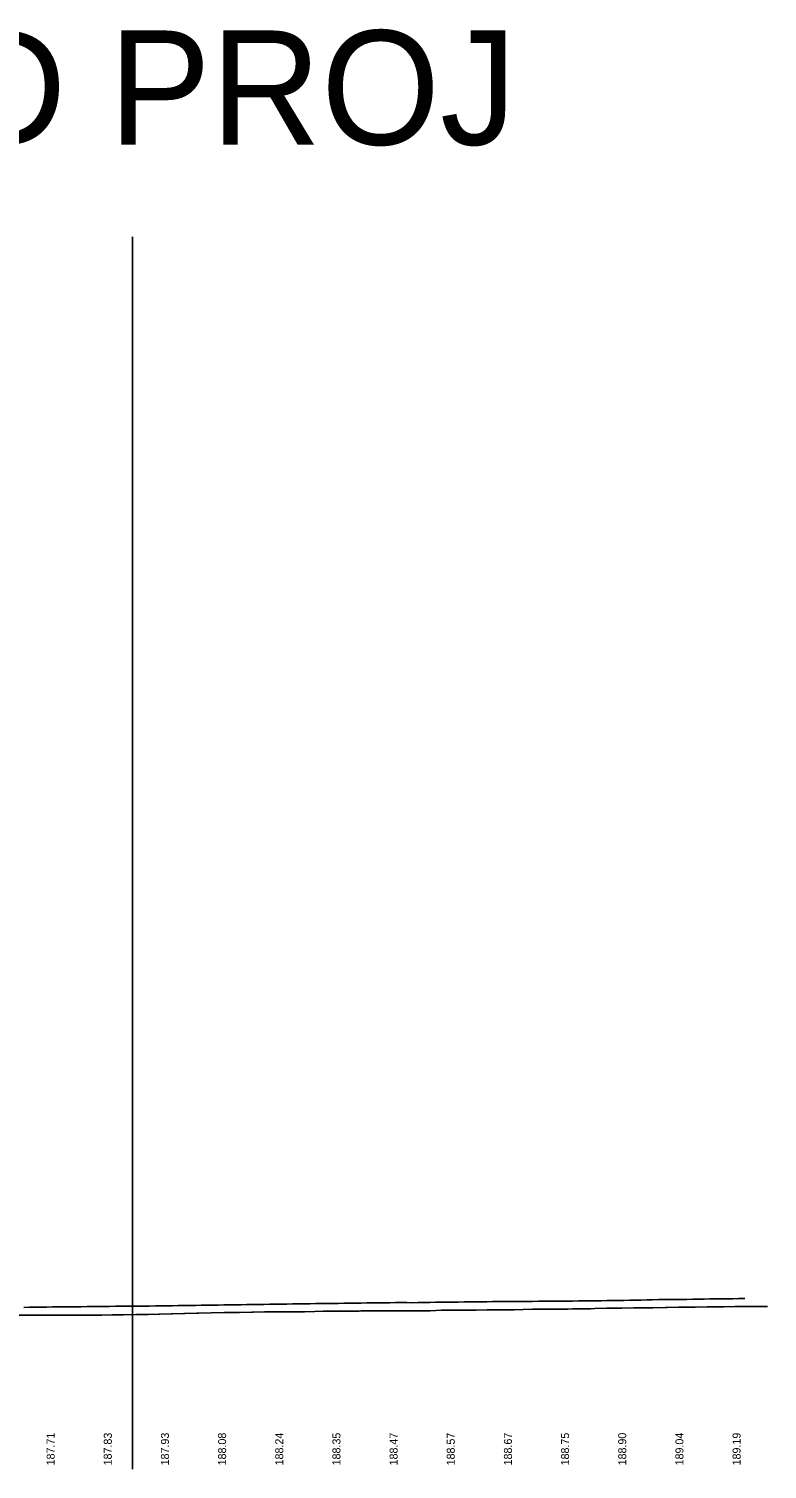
# Model space of a CAD drawing. Extents: x 1838386 to 1955906, y 719739 to 834437.
# Drawn here: x 1884140 to 1884785, y 820597 to 821857 of the extents above; entities that cross this region are included whole.
import ezdxf

# ---------------------------------------------------------------- set-up
doc = ezdxf.new("R2010")
doc.units = 0
for name, color, linetype in [('RD_DDB_Profile_EX', 7, 'Continuous'), ('RD_DDB_StripGrade', 7, 'Continuous'), ('RD_Sketch1', 7, 'Continuous')]:
    doc.layers.add(name, color=color, linetype=linetype)

msp = doc.modelspace()

# ---------------------------------------------------------------- linework, layer by layer
at = {"layer": 'RD_DDB_Profile_EX'}
for points in [[(1884135.2, 820738.3), (1884140.2, 820738.4), (1884145.2, 820738.5), (1884150.2, 820738.5), (1884155.2, 820738.6), (1884160.2, 820738.7), (1884165.2, 820738.7), (1884170.2, 820738.8), (1884175.2, 820738.8), (1884180.2, 820738.9), (1884185.2, 820738.9), (1884190.2, 820739), (1884195.2, 820739), (1884200.2, 820739.1), (1884205.2, 820739.1), (1884210.2, 820739.2), (1884215.2, 820739.3), (1884220.2, 820739.4), (1884225.2, 820739.4), (1884230.2, 820739.4), (1884235.2, 820739.4), (1884240.2, 820739.5), (1884245.2, 820739.5), (1884250.2, 820739.6), (1884255.2, 820739.6), (1884260.2, 820739.7), (1884265.2, 820739.8), (1884270.2, 820739.9), (1884275.2, 820740), (1884280.2, 820740), (1884285.2, 820740.1), (1884290.2, 820740.2), (1884295.2, 820740.3), (1884300.2, 820740.4), (1884305.2, 820740.4), (1884310.2, 820740.5), (1884315.2, 820740.6), (1884320.2, 820740.6), (1884325.2, 820740.7), (1884330.2, 820740.8), (1884335.2, 820740.9), (1884340.2, 820741), (1884345.2, 820741), (1884350.2, 820741.1), (1884355.2, 820741.2), (1884360.2, 820741.3), (1884365.2, 820741.3), (1884370.2, 820741.4), (1884375.2, 820741.5), (1884380.2, 820741.5), (1884385.2, 820741.5), (1884390.2, 820741.6)], [(1884390.2, 820741.6), (1884395.2, 820741.7), (1884400.2, 820741.7), (1884405.2, 820741.8), (1884410.2, 820741.8), (1884415.2, 820741.9), (1884420.2, 820742), (1884425.2, 820742.1), (1884430.2, 820742.1), (1884435.2, 820742.2), (1884440.2, 820742.3), (1884445.2, 820742.3), (1884450.2, 820742.4), (1884455.2, 820742.4), (1884460.2, 820742.5), (1884465.2, 820742.5), (1884470.2, 820742.5), (1884475.2, 820742.4), (1884480.2, 820742.5), (1884485.2, 820742.6), (1884490.2, 820742.7), (1884495.2, 820742.8), (1884500.2, 820742.8), (1884505.2, 820742.8), (1884510.2, 820742.9), (1884515.2, 820743), (1884520.2, 820743.1), (1884525.2, 820743.1), (1884530.2, 820743.1), (1884535.2, 820743.2), (1884540.2, 820743.3), (1884545.2, 820743.4), (1884550.2, 820743.4), (1884555.2, 820743.4), (1884560.2, 820743.5), (1884565.2, 820743.5), (1884570.2, 820743.5), (1884575.2, 820743.6), (1884580.2, 820743.6), (1884585.2, 820743.7), (1884590.2, 820743.7), (1884595.2, 820743.8), (1884600.2, 820743.8), (1884605.2, 820743.8), (1884610.2, 820743.9), (1884615.2, 820743.9), (1884620.2, 820744), (1884625.2, 820744), (1884630.2, 820744.1), (1884635.2, 820744.1), (1884640.2, 820744.2), (1884645.2, 820744.3), (1884650.2, 820744.3), (1884655.2, 820744.4), (1884660.2, 820744.5), (1884665.2, 820744.7), (1884670.2, 820744.7), (1884675.2, 820744.8), (1884680.2, 820744.9), (1884685.2, 820745), (1884690.2, 820745.1), (1884695.2, 820745.2), (1884700.2, 820745.2), (1884705.2, 820745.3), (1884710.2, 820745.3), (1884715.2, 820745.3), (1884720.2, 820745.4), (1884725.2, 820745.5), (1884730.2, 820745.6), (1884735.2, 820745.7), (1884740.2, 820745.7), (1884745.2, 820745.8), (1884750.2, 820745.9), (1884755.2, 820745.9), (1884760.2, 820746), (1884765.2, 820746.1), (1884765.7, 820746.1)]]:
    msp.add_lwpolyline(points, dxfattribs=at)
at = {"layer": 'RD_Sketch1'}
msp.add_line((1884230.2, 820596.8), (1884230.2, 821674.8), dxfattribs=at)
msp.add_line((1884230.2, 820596.8), (1884230.2, 821674.8), dxfattribs=at)
msp.add_line((1884230.2, 820596.8), (1884230.2, 821674.8), dxfattribs=at)
msp.add_lwpolyline([(1884131.1, 820731.4), (1884141.9, 820731.5), (1884142.4, 820731.5), (1884154.1, 820731.6), (1884155.1, 820731.6), (1884166, 820731.6), (1884167.4, 820731.6), (1884178.1, 820731.6), (1884179.7, 820731.6), (1884191.2, 820731.5), (1884192.7, 820731.5), (1884202.7, 820731.6), (1884203.5, 820731.6), (1884212.4, 820731.7), (1884213.1, 820731.7), (1884221.2, 820731.8), (1884222, 820731.8), (1884233.2, 820732), (1884233.6, 820732), (1884243.8, 820732.2), (1884244.2, 820732.2), (1884253.2, 820732.4), (1884254, 820732.4), (1884264, 820732.6), (1884264.9, 820732.6), (1884275.2, 820732.9), (1884276.4, 820732.9), (1884286.5, 820733.3), (1884287.9, 820733.3), (1884298.9, 820733.5), (1884310.3, 820733.8), (1884311.7, 820733.8), (1884322.5, 820733.9), (1884323.7, 820734), (1884334.6, 820734.1), (1884336.1, 820734.1), (1884345.7, 820734.4), (1884346.9, 820734.4), (1884357.5, 820734.5), (1884358.9, 820734.5), (1884359.7, 820734.5), (1884377.8, 820734.6), (1884379.2, 820734.6), (1884380.6, 820734.6), (1884389.8, 820734.7), (1884396.9, 820734.9), (1884398.4, 820734.9), (1884407.6, 820735), (1884408.5, 820735), (1884410.1, 820735), (1884420.8, 820735), (1884428.4, 820735.1), (1884429.8, 820735.2), (1884439.6, 820735.2), (1884441, 820735.2), (1884442, 820735.2), (1884456.8, 820735.3), (1884458.1, 820735.3), (1884471.4, 820735.2), (1884474.2, 820735.2), (1884477.2, 820735.2), (1884490.6, 820735.4), (1884500.6, 820735.8), (1884504.2, 820735.8), (1884513.9, 820735.8), (1884517.7, 820735.9), (1884527.1, 820735.9), (1884530.9, 820735.9), (1884540.3, 820736.1), (1884548.6, 820736.1), (1884552.5, 820736.2), (1884560.4, 820736.2), (1884564.2, 820736.3), (1884572, 820736.5), (1884580.4, 820736.7), (1884583.8, 820736.7), (1884590.6, 820736.7), (1884600, 820736.8), (1884604.1, 820736.9), (1884611, 820736.9), (1884615, 820737), (1884622, 820737.1), (1884622.9, 820737.1), (1884630.9, 820737.2), (1884634.6, 820737.3), (1884644.8, 820737.6), (1884648.3, 820737.6), (1884658.1, 820737.8), (1884668.6, 820738), (1884670.7, 820738), (1884682, 820738.1), (1884684, 820738.1), (1884685.4, 820738.1), (1884696.2, 820738.3), (1884697.9, 820738.3), (1884707.7, 820738.4), (1884709.4, 820738.4), (1884720.6, 820738.6), (1884722.3, 820738.6), (1884733, 820738.7), (1884734.8, 820738.7), (1884745.1, 820738.9), (1884747.6, 820738.9), (1884757.1, 820739), (1884759.5, 820739), (1884770, 820739.2), (1884773, 820739.2), (1884782.9, 820739.2), (1884785.6, 820739.2)], dxfattribs=at)
msp.add_lwpolyline([(1884131.1, 820731.4), (1884141.9, 820731.5), (1884142.4, 820731.5), (1884154.1, 820731.6), (1884155.1, 820731.6), (1884166, 820731.6), (1884167.4, 820731.6), (1884178.1, 820731.6), (1884179.7, 820731.6), (1884191.2, 820731.5), (1884192.7, 820731.5), (1884202.7, 820731.6), (1884203.5, 820731.6), (1884212.4, 820731.7), (1884213.1, 820731.7), (1884221.2, 820731.8), (1884222, 820731.8), (1884233.2, 820732), (1884233.6, 820732), (1884243.8, 820732.2), (1884244.2, 820732.2), (1884253.2, 820732.4), (1884254, 820732.4), (1884264, 820732.6), (1884264.9, 820732.6), (1884275.2, 820732.9), (1884276.4, 820732.9), (1884286.5, 820733.3), (1884287.9, 820733.3), (1884298.9, 820733.5), (1884310.3, 820733.8), (1884311.7, 820733.8), (1884322.5, 820733.9), (1884323.7, 820734), (1884334.6, 820734.1), (1884336.1, 820734.1), (1884345.7, 820734.4), (1884346.9, 820734.4), (1884357.5, 820734.5), (1884358.9, 820734.5), (1884359.7, 820734.5), (1884377.8, 820734.6), (1884379.2, 820734.6), (1884380.6, 820734.6), (1884389.8, 820734.7), (1884396.9, 820734.9), (1884398.4, 820734.9), (1884407.6, 820735), (1884408.5, 820735), (1884410.1, 820735), (1884420.8, 820735), (1884428.4, 820735.1), (1884429.8, 820735.2), (1884439.6, 820735.2), (1884441, 820735.2), (1884442, 820735.2), (1884456.8, 820735.3), (1884458.1, 820735.3), (1884471.4, 820735.2), (1884474.2, 820735.2), (1884477.2, 820735.2), (1884490.6, 820735.4), (1884500.6, 820735.8), (1884504.2, 820735.8), (1884513.9, 820735.8), (1884517.7, 820735.9), (1884527.1, 820735.9), (1884530.9, 820735.9), (1884540.3, 820736.1), (1884548.6, 820736.1), (1884552.5, 820736.2), (1884560.4, 820736.2), (1884564.2, 820736.3), (1884572, 820736.5), (1884580.4, 820736.7), (1884583.8, 820736.7), (1884590.6, 820736.7), (1884600, 820736.8), (1884604.1, 820736.9), (1884611, 820736.9), (1884615, 820737), (1884622, 820737.1), (1884622.9, 820737.1), (1884630.9, 820737.2), (1884634.6, 820737.3), (1884644.8, 820737.6), (1884648.3, 820737.6), (1884658.1, 820737.8), (1884668.6, 820738), (1884670.7, 820738), (1884682, 820738.1), (1884684, 820738.1), (1884685.4, 820738.1), (1884696.2, 820738.3), (1884697.9, 820738.3), (1884707.7, 820738.4), (1884709.4, 820738.4), (1884720.6, 820738.6), (1884722.3, 820738.6), (1884733, 820738.7), (1884734.8, 820738.7), (1884745.1, 820738.9), (1884747.6, 820738.9), (1884757.1, 820739), (1884759.5, 820739), (1884770, 820739.2), (1884773, 820739.2), (1884782.9, 820739.2), (1884785.6, 820739.2)], dxfattribs=at)
msp.add_lwpolyline([(1884131.1, 820731.4), (1884141.9, 820731.5), (1884142.4, 820731.5), (1884154.1, 820731.6), (1884155.1, 820731.6), (1884166, 820731.6), (1884167.4, 820731.6), (1884178.1, 820731.6), (1884179.7, 820731.6), (1884191.2, 820731.5), (1884192.7, 820731.5), (1884202.7, 820731.6), (1884203.5, 820731.6), (1884212.4, 820731.7), (1884213.1, 820731.7), (1884221.2, 820731.8), (1884222, 820731.8), (1884233.2, 820732), (1884233.6, 820732), (1884243.8, 820732.2), (1884244.2, 820732.2), (1884253.2, 820732.4), (1884254, 820732.4), (1884264, 820732.6), (1884264.9, 820732.6), (1884275.2, 820732.9), (1884276.4, 820732.9), (1884286.5, 820733.3), (1884287.9, 820733.3), (1884298.9, 820733.5), (1884310.3, 820733.8), (1884311.7, 820733.8), (1884322.5, 820733.9), (1884323.7, 820734), (1884334.6, 820734.1), (1884336.1, 820734.1), (1884345.7, 820734.4), (1884346.9, 820734.4), (1884357.5, 820734.5), (1884358.9, 820734.5), (1884359.7, 820734.5), (1884377.8, 820734.6), (1884379.2, 820734.6), (1884380.6, 820734.6), (1884389.8, 820734.7), (1884396.9, 820734.9), (1884398.4, 820734.9), (1884407.6, 820735), (1884408.5, 820735), (1884410.1, 820735), (1884420.8, 820735), (1884428.4, 820735.1), (1884429.8, 820735.2), (1884439.6, 820735.2), (1884441, 820735.2), (1884442, 820735.2), (1884456.8, 820735.3), (1884458.1, 820735.3), (1884471.4, 820735.2), (1884474.2, 820735.2), (1884477.2, 820735.2), (1884490.6, 820735.4), (1884500.6, 820735.8), (1884504.2, 820735.8), (1884513.9, 820735.8), (1884517.7, 820735.9), (1884527.1, 820735.9), (1884530.9, 820735.9), (1884540.3, 820736.1), (1884548.6, 820736.1), (1884552.5, 820736.2), (1884560.4, 820736.2), (1884564.2, 820736.3), (1884572, 820736.5), (1884580.4, 820736.7), (1884583.8, 820736.7), (1884590.6, 820736.7), (1884600, 820736.8), (1884604.1, 820736.9), (1884611, 820736.9), (1884615, 820737), (1884622, 820737.1), (1884622.9, 820737.1), (1884630.9, 820737.2), (1884634.6, 820737.3), (1884644.8, 820737.6), (1884648.3, 820737.6), (1884658.1, 820737.8), (1884668.6, 820738), (1884670.7, 820738), (1884682, 820738.1), (1884684, 820738.1), (1884685.4, 820738.1), (1884696.2, 820738.3), (1884697.9, 820738.3), (1884707.7, 820738.4), (1884709.4, 820738.4), (1884720.6, 820738.6), (1884722.3, 820738.6), (1884733, 820738.7), (1884734.8, 820738.7), (1884745.1, 820738.9), (1884747.6, 820738.9), (1884757.1, 820739), (1884759.5, 820739), (1884770, 820739.2), (1884773, 820739.2), (1884782.9, 820739.2), (1884785.6, 820739.2)], dxfattribs=at)

# ---------------------------------------------------------------- texts
at = {"layer": 'RD_DDB_StripGrade'}
for s, p in [('187.71', (1884162.1, 820600.1)), ('187.83', (1884212.1, 820600.1)), ('187.93', (1884262.1, 820600.1)), ('188.08', (1884312.1, 820600.1)), ('188.24', (1884362.1, 820600.1)), ('188.35', (1884412.1, 820600.1)), ('188.47', (1884462.1, 820600.1)), ('188.57', (1884512.1, 820600.1)), ('188.67', (1884562.1, 820600.1)), ('188.75', (1884612.1, 820600.1)), ('188.90', (1884662.1, 820600.1)), ('189.04', (1884712.1, 820600.1)), ('189.19', (1884762.1, 820600.1))]:
    msp.add_text(s, height=7, rotation=90, dxfattribs=at).set_placement(p)
at = {"layer": 'RD_Sketch1'}
msp.add_text('END PROJ', height=100, dxfattribs=at).set_placement((1883890, 821755.4))
msp.add_text('END PROJ', height=100, dxfattribs=at).set_placement((1883890, 821755.4))
msp.add_text('END PROJ', height=100, dxfattribs=at).set_placement((1883890, 821755.4))

doc.saveas('drawing.dxf')
